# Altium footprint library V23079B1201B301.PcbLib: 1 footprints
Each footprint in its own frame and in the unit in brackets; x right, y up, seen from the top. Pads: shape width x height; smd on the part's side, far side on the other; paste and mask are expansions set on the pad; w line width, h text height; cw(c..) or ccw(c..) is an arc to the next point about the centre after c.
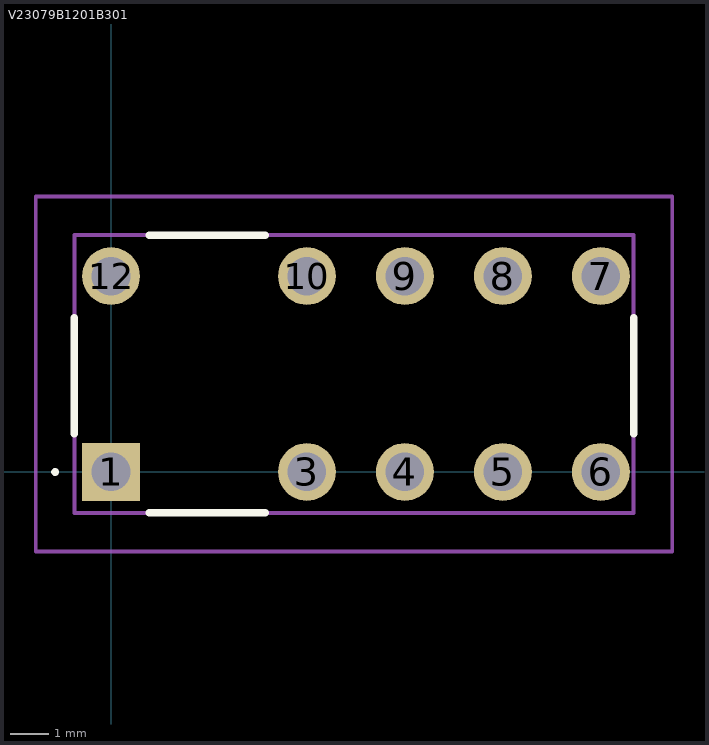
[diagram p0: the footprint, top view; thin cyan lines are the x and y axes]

## V23079B1201B301 [mm]
pads (10):
  rect 1.5x1.5 hole 1: 1(0,0)
  round 1.5 hole 1: 3(5.08,0) 4(7.62,0) 5(10.16,0) 6(12.7,0) 7(12.7,5.08) 8(10.16,5.08) 9(7.62,5.08) 10(5.08,5.08) 12(0,5.08)
Top Overlay:
  lines w0.1: -1.5,0 -1.5,0 ; -1.5,0 ccw(c-1.45,0) -1.4,0 ; -1.5,0 cw(c-1.45,0) -1.4,0 ; -1.4,0 -1.4,0
  lines w0.2: -0.95,1 -0.95,4 ; 1,-1.06 4,-1.06 ; 1,6.14 4,6.14 ; 13.55,1 13.55,4
Mechanical 15:
  lines w0.1: -0.95,-1.06 13.55,-1.06 13.55,6.14 -0.95,6.14 -0.95,-1.06
Mechanical 20:
  lines w0.1: -1.95,-2.06 14.55,-2.06 14.55,7.14 -1.95,7.14 -1.95,-2.06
